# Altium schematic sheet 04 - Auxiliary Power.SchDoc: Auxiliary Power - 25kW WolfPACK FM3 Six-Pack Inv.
size 431 x 279 mm; Date: 09/2024; DocumentNumber: CRD25DA12N-FMC; Revision: 2.0; SheetNumber: 4; SheetTotal: 9; SheetSize: B
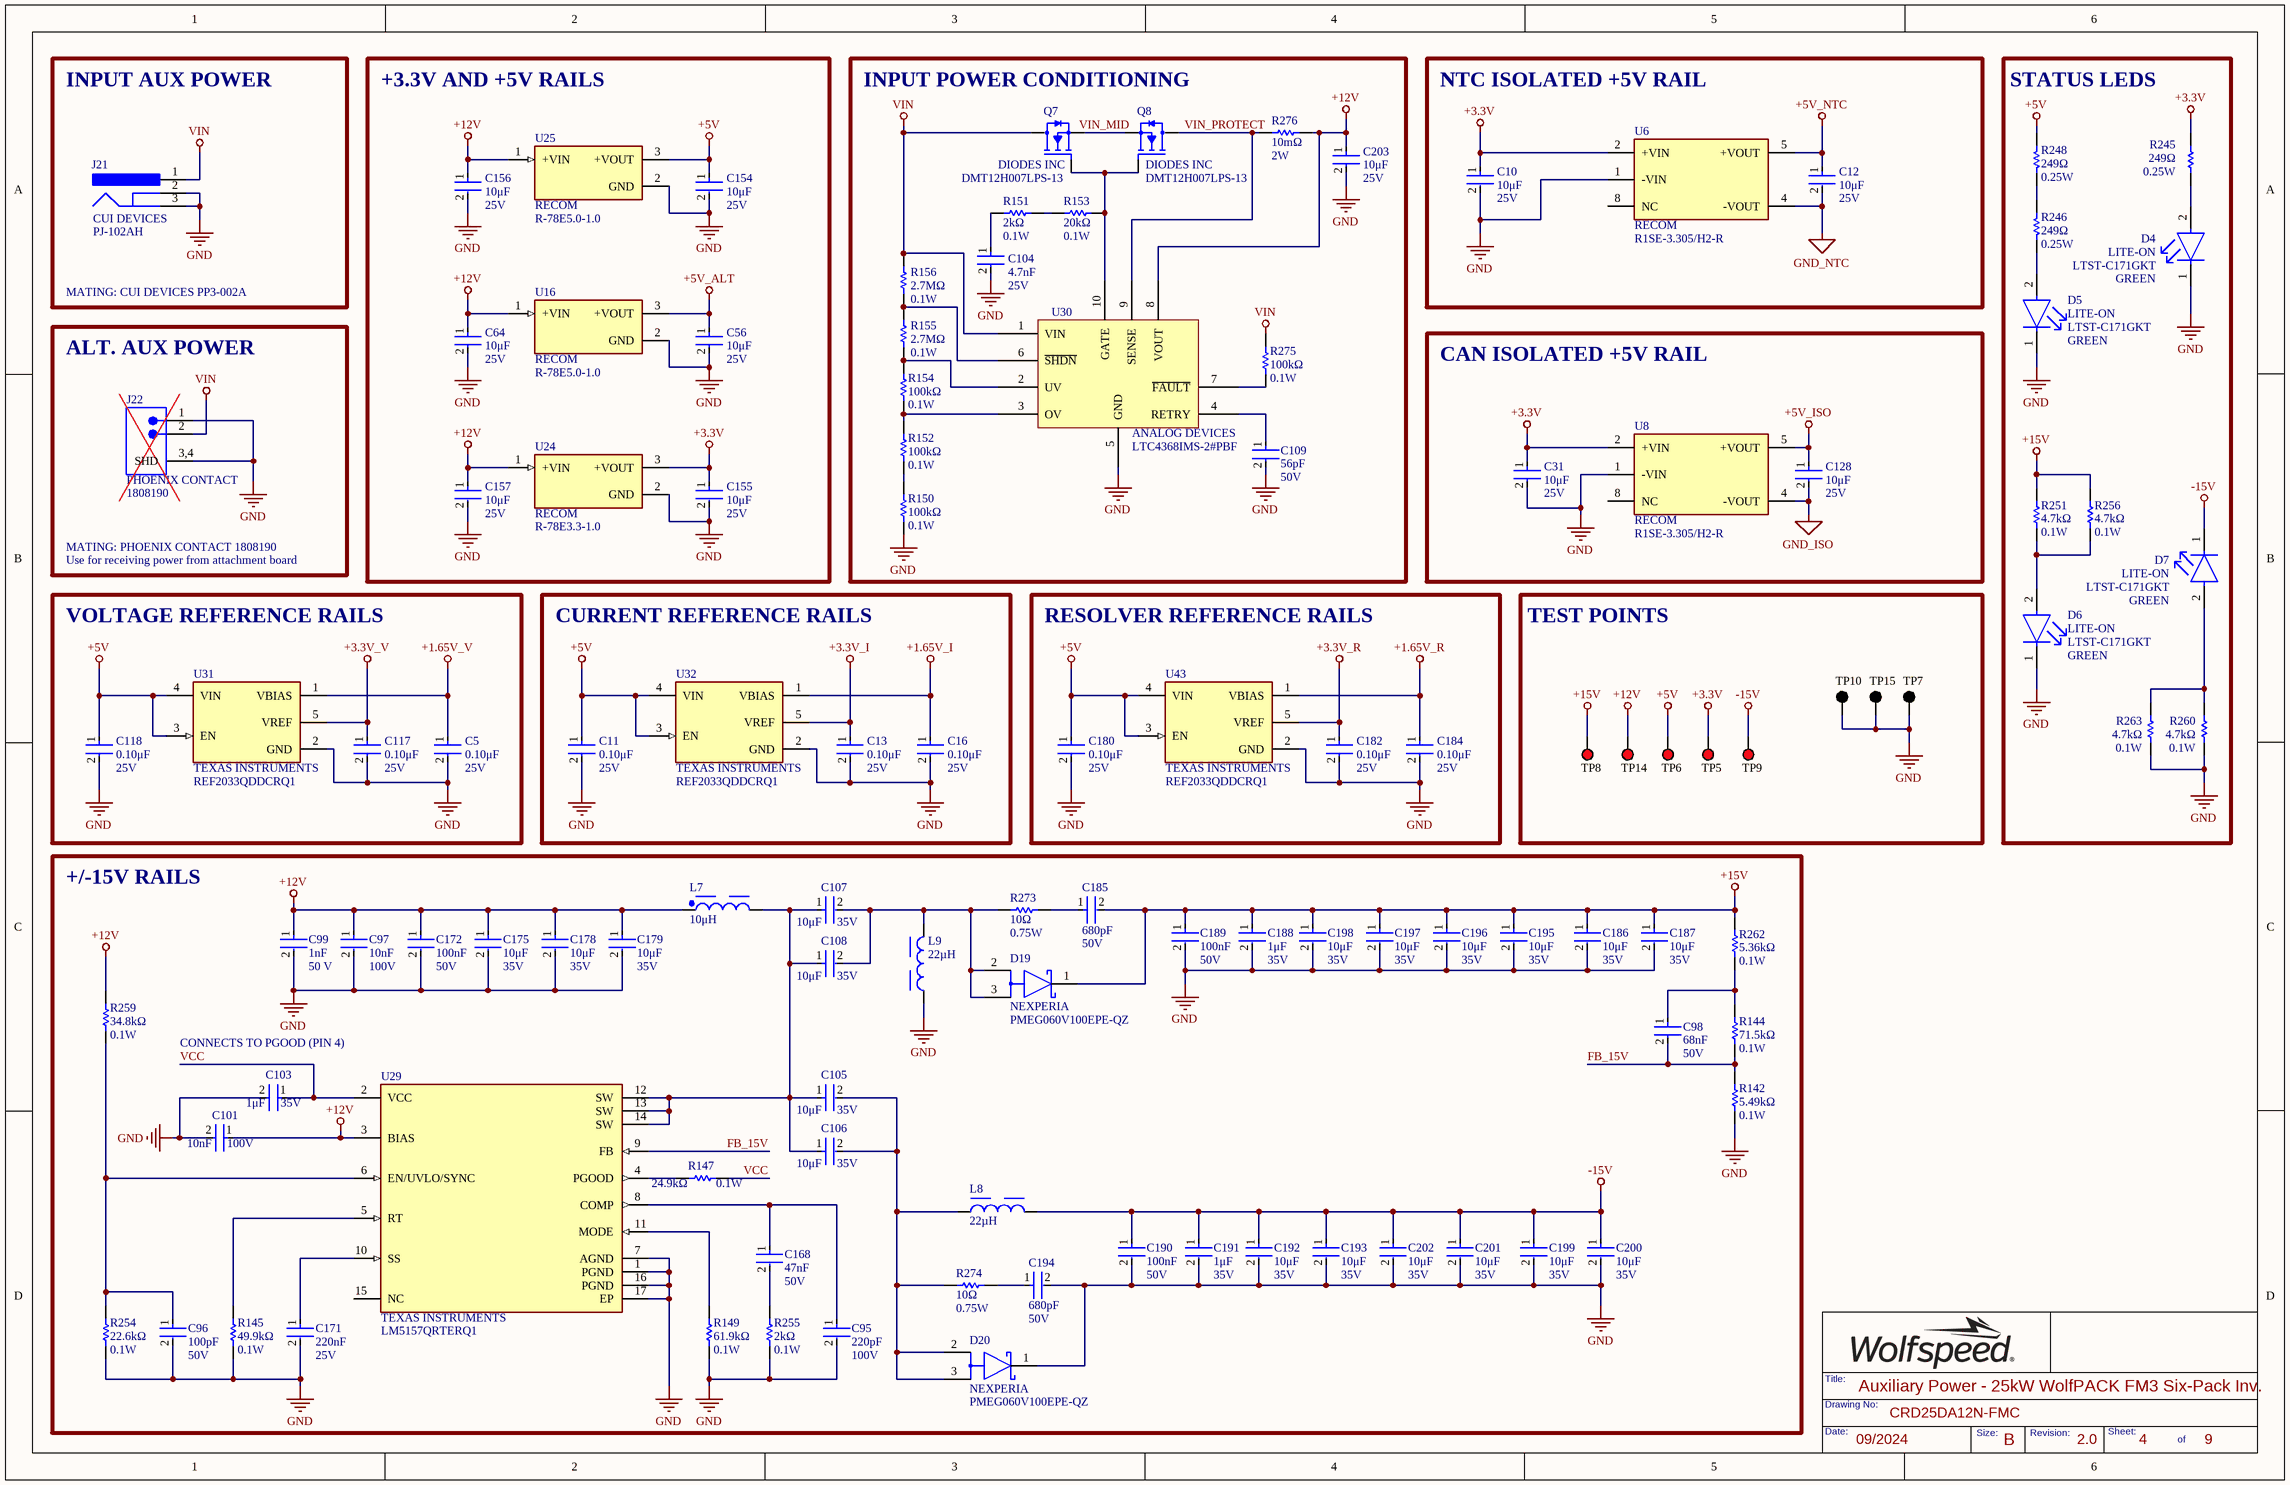
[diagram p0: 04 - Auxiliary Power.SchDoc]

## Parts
C5  Voltage Rating: 25V  Capacitance: 0.10μF  [FP-C0603C-CF-IPC_B]  (hidden comment: C0603C104K3RACTU)
C10  Voltage Rating: 25V  Capacitance: 10μF  [FP-CL31-IPC_B]  (hidden comment: CL31B106KAHSFNE)
C11  Voltage Rating: 25V  Capacitance: 0.10μF  [FP-C0603C-CF-IPC_B]  (hidden comment: C0603C104K3RACTU)
C12  Voltage Rating: 25V  Capacitance: 10μF  [FP-CL31-IPC_B]  (hidden comment: CL31B106KAHSFNE)
C13  Voltage Rating: 25V  Capacitance: 0.10μF  [FP-C0603C-CF-IPC_B]  (hidden comment: C0603C104K3RACTU)
C16  Voltage Rating: 25V  Capacitance: 0.10μF  [FP-C0603C-CF-IPC_B]  (hidden comment: C0603C104K3RACTU)
C31  Voltage Rating: 25V  Capacitance: 10μF  [FP-CL31-IPC_B]  (hidden comment: CL31B106KAHSFNE)
C56  Voltage Rating: 25V  Capacitance: 10μF  [FP-CL31-IPC_B]  (hidden comment: CL31B106KAHSFNE)
C64  Voltage Rating: 25V  Capacitance: 10μF  [FP-CL31-IPC_B]  (hidden comment: CL31B106KAHSFNE)
C95  value 220pF  Voltage Rating: 100V  [FP-C0603C-CF-IPC_B]  (hidden comment: GCM1885C2A221JA16D)
C96  Capacitance: 100pF  Voltage: 50V  [FP-C0603C-CF-IPC_B]  (hidden comment: CL10C101JB8NNNC)
C97  value 10nF  Voltage Rating: 100V  [FP-C0603C-CF-IPC_B]  (hidden comment: GCM188R72A103KA37D)
C98  value 68nF  Voltage Rating (DC): 50V  [FP-C0603C-CF-IPC_B]  (hidden comment: CGA3E2X7R1H683K080AA)
C99  Capacitance: 1nF  Voltage Rating: 50 V  [FP-C0603C-CF-IPC_B]  (hidden comment: C0603C102K5RACAUTO)
C101  value 10nF  Voltage Rating: 100V  [FP-C0603C-CF-IPC_B]  (hidden comment: GCM188R72A103KA37D)
C103  value 1μF  Voltage Rating: 35V  [FP-C0603C-CF-IPC_B]  (hidden comment: CGA3E1X7R1V105K080AC)
C104  Voltage Rating: 25V  Capacitance: 4.7nF  [FP-C0603C-CF-IPC_B]  (hidden comment: C0603C472K3RAC7867)
C105  value 10μF  Voltage Rating: 35V  [FP-C0603C-CF-IPC_B]  (hidden comment: GRM188R6YA106MA73D)
C106  value 10μF  Voltage Rating: 35V  [FP-C0603C-CF-IPC_B]  (hidden comment: GRM188R6YA106MA73D)
C107  value 10μF  Voltage Rating: 35V  [FP-C0603C-CF-IPC_B]  (hidden comment: GRM188R6YA106MA73D)
C108  value 10μF  Voltage Rating: 35V  [FP-C0603C-CF-IPC_B]  (hidden comment: GRM188R6YA106MA73D)
C109  Capacitance: 56pF  Voltage Rating: 50V  [FP-C0603C-CF-IPC_B]  (hidden comment: CL10C560JB8NNNC)
C117  Voltage Rating: 25V  Capacitance: 0.10μF  [FP-C0603C-CF-IPC_B]  (hidden comment: C0603C104K3RACTU)
C118  Voltage Rating: 25V  Capacitance: 0.10μF  [FP-C0603C-CF-IPC_B]  (hidden comment: C0603C104K3RACTU)
C128  Voltage Rating: 25V  Capacitance: 10μF  [FP-CL31-IPC_B]  (hidden comment: CL31B106KAHSFNE)
C154  Voltage Rating: 25V  Capacitance: 10μF  [FP-CL31-IPC_B]  (hidden comment: CL31B106KAHSFNE)
C155  Voltage Rating: 25V  Capacitance: 10μF  [FP-CL31-IPC_B]  (hidden comment: CL31B106KAHSFNE)
C156  Voltage Rating: 25V  Capacitance: 10μF  [FP-CL31-IPC_B]  (hidden comment: CL31B106KAHSFNE)
C157  Voltage Rating: 25V  Capacitance: 10μF  [FP-CL31-IPC_B]  (hidden comment: CL31B106KAHSFNE)
C168  value 47nF  Voltage Rating: 50V  [FP-C0603C-CF-IPC_B]  (hidden comment: CGA3E2X7R1H473K080AA)
C171  Capacitance: 220nF  Voltage: 25V  [FP-C0603C-CF-IPC_B]  (hidden comment: GCM188R71E224KA55D)
C172  value 100nF  Voltage: 50V  [FP-C0603C-CF-IPC_B]  (hidden comment: CGA3E2X7R1H104K080AA)
C175  value 10μF  Voltage Rating: 35V  [FP-C0603C-CF-IPC_B]  (hidden comment: GRM188R6YA106MA73D)
C178  value 10μF  Voltage Rating: 35V  [FP-C0603C-CF-IPC_B]  (hidden comment: GRM188R6YA106MA73D)
C179  value 10μF  Voltage Rating: 35V  [FP-C0603C-CF-IPC_B]  (hidden comment: GRM188R6YA106MA73D)
C180  Voltage Rating: 25V  Capacitance: 0.10μF  [FP-C0603C-CF-IPC_B]  (hidden comment: C0603C104K3RACTU)
C182  Voltage Rating: 25V  Capacitance: 0.10μF  [FP-C0603C-CF-IPC_B]  (hidden comment: C0603C104K3RACTU)
C184  Voltage Rating: 25V  Capacitance: 0.10μF  [FP-C0603C-CF-IPC_B]  (hidden comment: C0603C104K3RACTU)
C185  value 680pF  Voltage: 50V  [FP-C0603C-CF-IPC_B]  (hidden comment: C0603C681J5GACTU)
C186  value 10μF  Voltage Rating: 35V  [FP-C0603C-CF-IPC_B]  (hidden comment: GRM188R6YA106MA73D)
C187  value 10μF  Voltage Rating: 35V  [FP-C0603C-CF-IPC_B]  (hidden comment: GRM188R6YA106MA73D)
C188  value 1μF  Voltage Rating: 35V  [FP-C0603C-CF-IPC_B]  (hidden comment: CGA3E1X7R1V105K080AC)
C189  value 100nF  Voltage: 50V  [FP-C0603C-CF-IPC_B]  (hidden comment: CGA3E2X7R1H104K080AA)
C190  value 100nF  Voltage: 50V  [FP-C0603C-CF-IPC_B]  (hidden comment: CGA3E2X7R1H104K080AA)
C191  value 1μF  Voltage Rating: 35V  [FP-C0603C-CF-IPC_B]  (hidden comment: CGA3E1X7R1V105K080AC)
C192  value 10μF  Voltage Rating: 35V  [FP-C0603C-CF-IPC_B]  (hidden comment: GRM188R6YA106MA73D)
C193  value 10μF  Voltage Rating: 35V  [FP-C0603C-CF-IPC_B]  (hidden comment: GRM188R6YA106MA73D)
C194  value 680pF  Voltage: 50V  [FP-C0603C-CF-IPC_B]  (hidden comment: C0603C681J5GACTU)
C195  value 10μF  Voltage Rating: 35V  [FP-C0603C-CF-IPC_B]  (hidden comment: GRM188R6YA106MA73D)
C196  value 10μF  Voltage Rating: 35V  [FP-C0603C-CF-IPC_B]  (hidden comment: GRM188R6YA106MA73D)
C197  value 10μF  Voltage Rating: 35V  [FP-C0603C-CF-IPC_B]  (hidden comment: GRM188R6YA106MA73D)
C198  value 10μF  Voltage Rating: 35V  [FP-C0603C-CF-IPC_B]  (hidden comment: GRM188R6YA106MA73D)
C199  value 10μF  Voltage Rating: 35V  [FP-C0603C-CF-IPC_B]  (hidden comment: GRM188R6YA106MA73D)
C200  value 10μF  Voltage Rating: 35V  [FP-C0603C-CF-IPC_B]  (hidden comment: GRM188R6YA106MA73D)
C201  value 10μF  Voltage Rating: 35V  [FP-C0603C-CF-IPC_B]  (hidden comment: GRM188R6YA106MA73D)
C202  value 10μF  Voltage Rating: 35V  [FP-C0603C-CF-IPC_B]  (hidden comment: GRM188R6YA106MA73D)
C203  Voltage Rating: 25V  Capacitance: 10μF  [FP-CL31-IPC_B]  (hidden comment: CL31B106KAHSFNE)
D4  value GREEN  Manufacturer: LITE-ON  [FP-LTST-C171GKT-MFG]  (hidden comment: LTST-C171GKT)
D5  value GREEN  Manufacturer: LITE-ON  [FP-LTST-C171GKT-MFG]  (hidden comment: LTST-C171GKT)
D6  value GREEN  Manufacturer: LITE-ON  [FP-LTST-C171GKT-MFG]  (hidden comment: LTST-C171GKT)
D7  value GREEN  Manufacturer: LITE-ON  [FP-LTST-C171GKT-MFG]  (hidden comment: LTST-C171GKT)
D19  Manufacturer: NEXPERIA  [FP-PSMC_TO-277A-MFG]  (hidden comment: PMEG060V100EPE-QZ)
D20  Manufacturer: NEXPERIA  [FP-PSMC_TO-277A-MFG]  (hidden comment: PMEG060V100EPE-QZ)
J21  PJ-102AH  Manufacturer Print: CUI DEVICES  [CUI-PJ-102B_V]
J22  Manufacturer: PHOENIX CONTACT  [1808190]  (hidden comment: 1808190)
L7  value 10μH  [WE-XHMI_8080_L8.8W8.3H7.8]  (hidden comment: 74439358100)
L8  value 22µH  [74437368220]  (hidden comment: 74437368220)
L9  value 22µH  [74437368220]  (hidden comment: 74437368220)
Q7  DMT12H007LPS-13  Manufacturer: DIODES INC  [FP-PowerDI5060-8-MFG]
Q8  DMT12H007LPS-13  Manufacturer: DIODES INC  [FP-PowerDI5060-8-MFG]
R142  value 5.49kΩ  Power Rating: 0.1W  [FP-MCR03-IPC_B]  (hidden comment: RC0603FR-075K49L)
R144  value 71.5kΩ  Max Power Dissipation: 0.1W  [FP-MCR03-IPC_B]  (hidden comment: RT0603DRE0771K5L)
R145  value 49.9kΩ  Power Rating: 0.1W  [FP-MCR03-IPC_B]  (hidden comment: RT0603FRE0749K9L)
R147  value 24.9kΩ  Power Rating: 0.1W  [FP-MCR03-IPC_B]  (hidden comment: RC0603FR-0724K9L)
R149  value 61.9kΩ  Power Rating: 0.1W  [FP-MCR03-IPC_B]  (hidden comment: RC0603FR-0761K9L)
R150  Resistance: 100kΩ  Power Rating: 0.1W  [FP-MCR03-IPC_B]  (hidden comment: RC0603FR-07100KL)
R151  Resistance: 2kΩ  Power Rating: 0.1W  [FP-MCR03-IPC_B]  (hidden comment: RT0603DRE072KL)
R152  Resistance: 100kΩ  Power Rating: 0.1W  [FP-MCR03-IPC_B]  (hidden comment: RC0603FR-07100KL)
R153  Resistance: 20kΩ  Power Rating: 0.1W  [FP-MCR03-IPC_B]  (hidden comment: CRCW060320K0FKTA)
R154  Resistance: 100kΩ  Power Rating: 0.1W  [FP-MCR03-IPC_B]  (hidden comment: RC0603FR-07100KL)
R155  Power Rating: 0.1W  Resistance: 2.7MΩ  [FP-MCR03-IPC_B]  (hidden comment: RC0603JR-072M7L)
R156  Power Rating: 0.1W  Resistance: 2.7MΩ  [FP-MCR03-IPC_B]  (hidden comment: RC0603JR-072M7L)
R245  Resistance: 249Ω  Power Rating: 0.25W  [FP-MCR18-IPC_A]  (hidden comment: RC1206FR-07249RL)
R246  Resistance: 249Ω  Power Rating: 0.25W  [FP-MCR18-IPC_A]  (hidden comment: RC1206FR-07249RL)
R248  Resistance: 249Ω  Power Rating: 0.25W  [FP-MCR18-IPC_A]  (hidden comment: RC1206FR-07249RL)
R251  Resistance: 4.7kΩ  Power Rating: 0.1W  [FP-MCR03-IPC_B]  (hidden comment: CRCW06034K70FKTA)
R254  value 22.6kΩ  Max Power Dissipation: 0.1W  [FP-MCR03-IPC_B]  (hidden comment: RT0603DRE0722K6L)
R255  Resistance: 2kΩ  Power Rating: 0.1W  [FP-MCR03-IPC_B]  (hidden comment: RT0603DRE072KL)
R256  Resistance: 4.7kΩ  Power Rating: 0.1W  [FP-MCR03-IPC_B]  (hidden comment: CRCW06034K70FKTA)
R259  value 34.8kΩ  Power Rating: 0.1W  [FP-MCR03-IPC_B]  (hidden comment: RT0603DRE0734K8L)
R260  Resistance: 4.7kΩ  Power Rating: 0.1W  [FP-MCR03-IPC_B]  (hidden comment: CRCW06034K70FKTA)
R262  value 5.36kΩ  Power Rating: 0.1W  [FP-MCR03-IPC_B]  (hidden comment: RT0603BRD075K36L)
R263  Resistance: 4.7kΩ  Power Rating: 0.1W  [FP-MCR03-IPC_B]  (hidden comment: CRCW06034K70FKTA)
R273  value 10Ω  Power Rating: 0.75W  [RESC3125X70X40NL20T20]  (hidden comment: CRCW121010R0FKEAHP)
R274  value 10Ω  Power Rating: 0.75W  [RESC3125X70X40NL20T20]  (hidden comment: CRCW121010R0FKEAHP)
R275  Resistance: 100kΩ  Power Rating: 0.1W  [FP-MCR03-IPC_B]  (hidden comment: RC0603FR-07100KL)
R276  Resistance: 10mΩ  Max Power Dissipation: 2W  [FP-RL2512-IPC_A]  (hidden comment: PE2512FKE7W0R01L)
TP5  5010  [KSTN-5010_V]  (value not drawn)
TP6  5010  [KSTN-5010_V]  (value not drawn)
TP7  5011  [KSTN-5011_V]  (value not drawn)
TP8  5010  [KSTN-5010_V]  (value not drawn)
TP9  5010  [KSTN-5010_V]  (value not drawn)
TP10  5011  [KSTN-5011_V]  (value not drawn)
TP14  5010  [KSTN-5010_V]  (value not drawn)
TP15  5011  [KSTN-5011_V]  (value not drawn)
U6  Manufacturer: RECOM  [FP-R1SE-0505-R-MFG]  (hidden comment: R1SE-3.305/H2-R)
U8  Manufacturer: RECOM  [FP-R1SE-0505-R-MFG]  (hidden comment: R1SE-3.305/H2-R)
U16  R-78E5.0-1.0  Manufacturer Print: RECOM  [CONV_R-78E5.0-1.0]
U24  R-78E3.3-1.0  Manufacturer Print: RECOM  [CONV_R-78E3.3-1.0]
U25  R-78E5.0-1.0  Manufacturer Print: RECOM  [CONV_R-78E5.0-1.0]
U29  Manufacturer: TEXAS INSTRUMENTS  [FP-RTE0016K-IPC_A]  (hidden comment: LM5157QRTERQ1)
U30  LTC4368IMS-2#PBF  Manufacturer Print: ANALOG DEVICES  [SOP50P490X110-10N]
U31  Manufacturer: TEXAS INSTRUMENTS  [FP-DDC0005A-MFG]  (hidden comment: REF2033QDDCRQ1)
U32  Manufacturer: TEXAS INSTRUMENTS  [FP-DDC0005A-MFG]  (hidden comment: REF2033QDDCRQ1)
U43  Manufacturer: TEXAS INSTRUMENTS  [FP-DDC0005A-MFG]  (hidden comment: REF2033QDDCRQ1)

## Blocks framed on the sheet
INPUT AUX POWER: J21
+3.3V AND +5V RAILS: C56 C64 C154-C157 U16 U24 U25
INPUT POWER CONDITIONING: C104 C109 C203 Q7 Q8 R150-R156 R275 R276 U30
NTC ISOLATED +5V RAIL: C10 C12 U6
STATUS LEDS: D4-D7 R245 R246 R248 R251 R256 R260 R263
ALT. AUX POWER: J22
CAN ISOLATED +5V RAIL: C31 C128 U8
VOLTAGE REFERENCE RAILS: C5 C117 C118 U31
CURRENT REFERENCE RAILS: C11 C13 C16 U32
RESOLVER REFERENCE RAILS: C180 C182 C184 U43
TEST POINTS: TP5-TP10 TP14 TP15
+/-15V RAILS: C95-C99 C101 C103 C105-C108 C168 C171 C172 C175 C178 C179 C185-C202 D19 D20 L7-L9 R142 R144 R145 R147 R149 R254 R255 R259 R262 R273 R274 U29

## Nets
+1.65V_I: C16.1 U32.1(VBIAS)
+1.65V_R: C184.1 U43.1(VBIAS)
+1.65V_V: C5.1 U31.1(VBIAS)
+3.3V: C10.1 C31.1 C155.1 R245.1 TP5.1 U6.2(+VIN) U8.2(+VIN) U24.3(+VOUT)
+3.3V_I: C13.1 U32.5(VREF)
+3.3V_R: C182.1 U43.5(VREF)
+3.3V_V: C117.1 U31.5(VREF)
+5V: C11.1 C118.1 C154.1 C180.1 R248.1 TP6.1 U25.3(+VOUT) U31.3(EN) U31.4(VIN) U32.3(EN) U32.4(VIN) U43.3(EN) U43.4(VIN)
+5V_ALT: C56.1 U16.3(+VOUT)
+5V_ISO: C128.1 U8.5(+VOUT)
+5V_NTC: C12.1 U6.5(+VOUT)
+12V: C64.1 C97.1 C99.1 C101.1 C156.1 C157.1 C172.1 C175.1 C178.1 C179.1 C203.1 L7.1 R259.2 R276.2 TP14.1 U16.1(+VIN) U24.1(+VIN) U25.1(+VIN) U29.3(BIAS) U30.8(VOUT)
+15V: C185.2 C186.1 C187.1 C188.1 C189.1 C195.1 C196.1 C197.1 C198.1 D19.1(K) R251.2 R256.2 R262.2 TP8.1
-15V: C190.1 C191.1 C192.1 C193.1 C199.1 C200.1 C201.1 C202.1 D7.1(C) L8.2 TP9.1
GND: C5.2 C10.2 C11.2 C13.2 C16.2 C31.2 C56.2 C64.2 C95.2 C96.2 C97.2 C99.2 C101.2 C103.2 C104.2 C109.2 C117.2 C118.2 C154.2 C155.2 C156.2 C157.2 C171.2 C172.2 C175.2 C178.2 C179.2 C180.2 C182.2 C184.2 C186.2 C187.2 C188.2 C189.2 C190.2 C191.2 C192.2 C193.2 C194.2 C195.2 C196.2 C197.2 C198.2 C199.2 C200.2 C201.2 C202.2 C203.2 D4.1(C) D5.1(C) D6.1(C) D20.1(K) J21.2 J21.3 J22.1 J22.3,4(SHD) L9.1 R142.1 R145.1 R149.1 R150.1 R254.1 R255.1 R260.1 R263.1 TP7.1 TP10.1 TP15.1 U6.1(-VIN) U8.1(-VIN) U16.2(GND) U24.2(GND) U25.2(GND) U29.1(PGND) U29.7(AGND) U29.16(PGND) U29.17(EP) U30.5(GND) U31.2(GND) U32.2(GND) U43.2(GND)
GND_ISO: C128.2 U8.4(-VOUT)
GND_NTC: C12.2 U6.4(-VOUT)
VIN: J21.1 J22.2 Q7.5(D) R156.2 R275.2 U30.1(VIN)
FB_15V: C98.2 R142.2 R144.1 U29.9(FB)
VCC: C103.1 R147.2 U29.2(VCC)
VIN_MID: Q7.1,2,3(S) Q8.1,2,3(S)
VIN_PROTECT: Q8.5(D) R276.1 U30.9(SENSE)
NetC95_1: C95.1 C168.1 U29.8(COMP)
NetC96_1: C96.1 R254.2 R259.1 U29.6(EN/UVLO/SYNC)
NetC98_1: C98.1 R144.2 R262.1
NetC104_1: C104.1 R151.1
NetC105_1: C105.1 C106.1 C107.1 C108.1 L7.2 U29.12(SW) U29.13(SW) U29.14(SW)
NetC105_2: C105.2 C106.2 D20.2(A) D20.3(A) L8.1 R274.1
NetC107_2: C107.2 C108.2 D19.2(A) D19.3(A) L9.2 R273.1
NetC109_1: C109.1 U30.4(RETRY)
NetC168_2: C168.2 R255.2
NetC171_1: C171.1 U29.10(SS)
NetC185_1: C185.1 R273.2
NetC194_1: C194.1 R274.2
NetD4_2: D4.2(A) R245.2
NetD5_2: D5.2(A) R246.2
NetD6_2: D6.2(A) R251.1 R256.1
NetD7_2: D7.2(A) R260.2 R263.2
NetQ7_4: Q7.4(G) Q8.4(G) R153.2 U30.10(GATE)
NetR145_2: R145.2 U29.5(RT)
NetR147_1: R147.1 U29.4(PGOOD)
NetR149_2: R149.2 U29.11(MODE)
NetR150_2: R150.2 R152.1
NetR151_2: R151.2 R153.1
NetR152_2: R152.2 R154.1 U30.3(OV)
NetR154_2: R154.2 R155.1 U30.2(UV)
NetR155_2: R155.2 R156.1 U30.6(~{SHDN})
NetR246_1: R246.1 R248.2
NetR275_1: R275.1 U30.7(~{FAULT})

Not connected (* = marked no-connect by the designer): U6 8(NC); U8 8(NC); U29 15(NC)

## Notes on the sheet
- MATING: CUI DEVICES PP3-002A
- MATING: PHOENIX CONTACT 1808190
- Use for receiving power from attachment board
- CONNECTS TO PGOOD (PIN 4)

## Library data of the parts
C5 C11 C13 C16 C117 C118 C180 C182 C184 = CMP-2006-03057-2: CAP CER 0.1UF 25V X7R 0603; Manufacturer: KEMET; Value: 0.10μF; Material: Ceramic; Tolerance: 0.1; Temperature Coefficient: 30ppm/°C; Automotive Grade: Grade 1
C10 C12 C31 C56 C64 C128 C154-C157 C203 = CMP-13271-001434-1: CAP CER 10UF 25V X7R 1206; Manufacturer: SAMSUNG; Tolerance: 10%; Value: 10μF
C95 = GCM1885C2A221JA16D: CAP CER 220PF 100V C0G/NP0 0603; Manufacturer: MURATA; Material: 4241ConductorMaterial; Tolerance: 5%; Dielectric: C0G; Dissipation Factor: 0.01%; Temperature Coefficient: 30ppm/°C
C96 = CL10C101JB8NNNC: CAP CER 100PF 50V C0G/NP0 0603; Manufacturer: SAMSUNG; Material: Ceramic; Tolerance: 5%; Dielectric: C0G; Temperature Coefficient: 300ppm/°C
C97 C101 = GCM188R72A103KA37D: CAP CER 10000PF 100V X7R 0603; Manufacturer: MURATA; Material: 4241ConductorMaterial; Tolerance: 10%
C98 = CGA3E2X7R1H683K080AA: CAP CER 0.068UF 50V X7R 0603; Manufacturer: TDK; Tolerance: 10%
C99 = CMP-2006-03716-2: CAP CER 1000PF 50V X7R 0603; Manufacturer: KEMET; Material: Ceramic; Automotive Grade: Grade 1; Value: 1nF; Tolerance: 0.1; Temperature Coefficient: 30ppm/°C
C103 C188 C191 = CGA3E1X7R1V105K080AC: CAP CER 1UF 35V X7R 0603; Manufacturer: TDK; Material: 4241ConductorMaterial; Tolerance: 10%
C104 = C0603C472K3RAC7867: CAP CER 4700PF 25V 10% X7R 0603; Manufacturer: KEMET; Manufacturer Part Number: C0603C472K3RACTU; Dielectric Material: Ceramic; Value: 4.7nF
C105-C108 C175 C178 C179 C186 C187 C192 C193 C195-C202 = GRM188R6YA106MA73D: CAP CER 10UF 35V X5R 0603; Manufacturer: MURATA; Material: 4241ConductorMaterial; Tolerance: 20%
C109 = CL10C560JB8NNNC: CAP CER 56PF 50V C0G/NP0 0603; Manufacturer: SAMSUNG; Material: Ceramic; Tolerance: 5%; Dielectric: C0G; Temperature Coefficient: 30ppm/°C
C168 = CGA3E2X7R1H473K080AA: CAP CER 0.047UF 50V X7R 0603; Manufacturer: TDK; Material: 4241ConductorMaterial; Tolerance: 10%
C171 = GCM188R71E224KA55D: CAP CER 0.22UF 25V X7R 0603; Manufacturer: MURATA; Material: 4241ConductorMaterial; Tolerance: 10%; Value: 220nF
C172 C189 C190 = CGA3E2X7R1H104K080AA: CAP CER 0.1UF 50V X7R 0603; Manufacturer: TDK; Material: 4241ConductorMaterial; Tolerance: 10%
C185 C194 = C0603C681J5GACTU: CAP CER 680PF 50V C0G/NP0 0603; Manufacturer: KEMET; Dielectric Material: Ceramic; Material: 4241ConductorMaterial; Tolerance: 5%; Dielectric: C0G; Temperature Coefficient: 30ppm/°C; Dissipation Factor: 0.1%
D4-D7 = CMP-22017-000007-1: LED GREEN CLEAR CHIP SMD; Luminous Intensity: 12mcd; Lens Color: Colorless; Dominant Wavelength: 569nm; Number of LEDs: 1; Power Dissipation: 100mW; Viewing Angle: 130°; Reverse Voltage: 5V; Test Current: 10mA; Forward Voltage: 2.1V; Wavelength: 585nm; Lens Style: Diffused; Forward Current: 30mA
D19 D20 = PMEG060V100EPE-QZ: DIODE SCHOTTKY 60V 10A CFP15B
J21 = PJ-102AH: CONN PWR JACK 2X5.5MM SOLDER; Gender: Male; Shielding: Unshielded; Current Rating: 5A; Voltage Rating: 24V; Insulation Resistance: 50MR; Number of Conductors: 2
J22 = 1808190: TERM BLOCK HDR 2POS 90DEG 2.5MM
L7 = 74439358100: FIXED IND 10UH 5.8A 20 MOHM SMD; Manufacturer: WURTH ELECTRONIK
L8 L9 = 74437368220: FIXED IND 22UH 3.5A 74 MOHM SMD; NexarPartId: 57062130; Manufacturer: WURTH ELECTRONIK; Tolerance: 20%; Series Resistance: 74mΩ; Saturation Current: 5A; DC Resistance (DCR): 64mΩ; Self Resonant Frequency: 7MHz; Test Frequency: 100kHz
Q7 Q8 = DMT12H007LPS-13: MOSFET N-CH 120V 90A PWRDI5060-8
R142 = RC0603FR-075K49L: RES 5.49K OHM 1% 1/10W 0603; Manufacturer: YAGEO; Temperature Coefficient: 100ppm/°C; Voltage Rating: 50V; Max Power Dissipation: 100mW
R144 = RT0603DRE0771K5L: RES SMD 71.5KOHM 0.5% 1/10W 0603; Manufacturer: YAGEO; Temperature Coefficient: 50ppm/°C; Voltage Rating (DC): 50V
R145 = RT0603FRE0749K9L: RES SMD 49.9K OHM 1% 1/10W 0603; Manufacturer: YAGEO; Temperature Coefficient: 50ppm/°C; Max Power Dissipation: 100mW; Voltage Rating: 75V; Voltage Rating (DC): 50V
R147 = RC0603FR-0724K9L: RES 24.9K OHM 1% 1/10W 0603; Manufacturer: YAGEO; Temperature Coefficient: 100ppm/°C; Max Power Dissipation: 100mW; Voltage Rating: 50V
R149 = RC0603FR-0761K9L: RES 61.9K OHM 1% 1/10W 0603; Manufacturer: YAGEO; Temperature Coefficient: 100ppm/°C; Max Power Dissipation: 100mW; Voltage Rating (DC): 50V; Working Voltage: 75V
R150 R152 R154 R275 = RC0603FR-07100KL: RES 100K OHM 1% 1/10W 0603; Manufacturer: YAGEO; Temperature Coefficient: 100ppm/°C; Voltage Rating: 50V; Working Voltage: 75V; Max Power Dissipation: 100mW; Value: 100kΩ
R151 R255 = RT0603DRE072KL: RES SMD 2K OHM 0.5% 1/10W 0603; Manufacturer: YAGEO; Temperature Coefficient: 50ppm/°C; Voltage Rating: 75V; Max Power Dissipation: 100mW; Voltage Rating (DC): 50V; Value: 2kΩ
R153 = CRCW060320K0FKTA: RES SMD 20K OHM 1% 1/10W 0603; Manufacturer: VISHAY DALE; Temperature Coefficient: 100ppm/°C; Voltage Rating: 75V; Max Power Dissipation: 100mW; Value: 20kΩ
R155 R156 = RC0603JR-072M7L: RES 2.7M OHM 5% 1/10W 0603; Manufacturer: YAGEO; Temperature Coefficient: 100ppm/°C; Voltage Rating: 75V; Max Power Dissipation: 100mW; Voltage Rating (DC): 50V; Value: 2.7MΩ
R245 R246 R248 = RC1206FR-07249RL: RES 249 OHM 1% 1/4W 1206; Manufacturer: YAGEO; Voltage Rating: 200V; Temperature Coefficient: 100ppm/°C; Max Power Dissipation: 250mW; Value: 249Ω
R251 R256 R260 R263 = CRCW06034K70FKTA: RES SMD 4.7K OHM 1% 1/10W 0603; Manufacturer: VISHAY DALE; Voltage Rating: 75V; Max Power Dissipation: 100mW; Temperature Coefficient: 100ppm/°C; Value: 4.7kΩ
R254 = RT0603DRE0722K6L: RES SMD 22.6KOHM 0.5% 1/10W 0603; Manufacturer: YAGEO; Temperature Coefficient: 50ppm/°C; Voltage Rating (DC): 50V
R259 = RT0603DRE0734K8L: RES SMD 34.8KOHM 0.5% 1/10W 0603; Manufacturer: YAGEO; Temperature Coefficient: 50ppm/°C; Voltage Rating: 75V; Voltage Rating (DC): 50V; Max Power Dissipation: 100mW
R262 = RT0603BRD075K36L: RES SMD 5.36KOHM 0.1% 1/10W 0603; Manufacturer: YAGEO; Temperature Coefficient: 25ppm/°C; Max Power Dissipation: 100mW; Voltage Rating: 75V; Voltage Rating (DC): 50V
R273 R274 = CRCW121010R0FKEAHP: RES SMD 10 OHM 1% 3/4W 1210; Manufacturer: VISHAY; Voltage Rating: 200V; Max Power Dissipation: 750mW; Temperature Coefficient: 100ppm/°C
R276 = PE2512FKE7W0R01L: RES 0.01 OHM 1% 2W 2512; Manufacturer: YAGEO; Temperature Coefficient: 50ppm/°C; Value: 10mΩ
TP5 TP6 TP8 TP9 TP14 = CMP-1672-00002-4: PC TEST POINT MULTIPURPOSE RED; Manufacturer: KEYSTONE
TP7 TP10 TP15 = CMP-1672-00003-4: PC TEST POINT MULTIPURPOSE BLACK; Manufacturer: KEYSTONE
U6 U8 = R1SE-3.305/H2-R: DC DC CONVERTER 5V 1W; Number of Outputs: 1; Min Input Voltage: 2.97V; Max Input Voltage: 3.63V; Max Output Current: 200mA; Isolation Voltage: 2kV; Efficiency: 75%
U16 U25 = R-78E5.0-1.0: DC DC CONVERTER 5V 5W; Number of Outputs: 1; Min Input Voltage: 8V; Max Input Voltage: 28V; Max Output Current: 1A; Efficiency: 91%
U24 = R-78E3.3-1.0: DC DC CONVERTER 3.3V 3W; Number of Outputs: 1; Min Input Voltage: 8V; Max Input Voltage: 28V; Max Output Current: 1A; Efficiency: 91%; Max Output Power: 3.3W; Min Input Voltage (DC): 7V
U29 = LM5157QRTERQ1: IC REG MULT CONFG ADJ 6.5A 16QFN
U30 = LTC4368IMS-2#PBF: IC SURGE SUPPRESSION ADJ 10MSOP
U31 U32 U43 = REF2033QDDCRQ1: AUTOMOTIVE LOW-DRIFT, LOW-POWER,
